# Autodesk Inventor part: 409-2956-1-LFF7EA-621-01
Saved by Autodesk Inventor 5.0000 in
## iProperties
Created: 2010-06
Part Number: 409-2956-1-LFF7EA-621-01
Cost Center: 0 lbmass
Material: A36 STEEL PLATE
Document SubType Name: Sheet Metal
Designer: S. Boerckel
Authority: 0 in^3
Mass: 6325.9 g
Surface Area: 869.505 cm^2
Volume: 804.822 cm^3
Density: 7.86 g/cm^3
Flat Pattern Width: 12.7 cm
Flat Pattern Length: 25.4 cm
Flat Pattern Area: 322.58 cm^2
Sheet Metal Rule: 1" HR PLATE
Sheet Metal Width: 10.0000 in
Sheet Metal Length: 50.0000 in^2
Description: STAINER FOOT PLATE
User Status: BURN
SaveDate: 2008-01-15
SaveTime: 10:24
FileName: Sheet Metal
Wide: =<Flat Pattern Width>cm
Length: =<Flat Pattern Length>cm
Thickness: 1.0000 in
SMR: =<Sheet Metal Rule> - <Material>
Author: S. Boerckel
Revision Number: 0
Subject: DEMIN WATER FORWARDING PUMP SKID-7EA
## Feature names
1. Hole1
2. Hole2
3. Plate1
